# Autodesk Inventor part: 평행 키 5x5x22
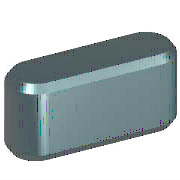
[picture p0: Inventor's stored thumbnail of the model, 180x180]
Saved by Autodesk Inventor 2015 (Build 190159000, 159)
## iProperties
IsCustomPart: 1
Created: 2012-02
Part Number: 평행 키 5x5x22
Material: 강철, 연강
Description: 평행 키
Document SubType Name: Modeling
Standard: JIS B 1301
Designer: mdu-01
Standards Organization: JIS
Language: ko-KR
Size Designation: 5x5x22
Categories: <MemberInstance><Categories><Category DisplayName="샤프트 부품" InternalName="7f7aeb1f-a693-4053-b835-cee3144e0d98" Mnemonic="SHFT"><Category DisplayName="키" Interna
Density: 1 g/cm^3
Appearance: 강철
Author: mdu-01
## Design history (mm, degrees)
workplane "Work Plane1"
workplane "Work Plane2"
sketch "스케치1"
  geometry: L1 (2.5, 2.5)-(19.5, 2.5); L2 (19.5, -2.5)-(2.5, -2.5); L3 (0, 9.4)-(0, -7.4) reference; L4 (-5, 0)-(30, 0) reference; L5 (22, 0)-(22, 7); A1 r 2.5 centre (2.5, 0) between (2.5, 2.5) and (2.5, -2.5); A2 r 2.5 centre (19.5, 0) between (19.5, -2.5) and (19.5, 2.5)
  constraints: 6 end point, 5 point on circle, 4 tangent, 3 point on line, 2 centre point, 1 horizontal, 1 parallel, 1 perpendicular
  dimensions: "d0" = 2.5 radius of A1 (= 0.5 x PB); "d13" = 2.5 radius of A2 (= 0.5 x PB); "d14" = 22 distance between parallel lines of L5 L3 (= NLG)
extrude "본체1" new body sketch "스케치1" taper "d3" = 0 deg; stored distance "d4" = 10
workplane "Work Plane3"
body "Solid1"
chamfer "모따기1" distance "d8" = 0.4 (= PHH); stored, may be unused: second distance "d9" = 0.4 (= PHH), angle "d15" = 45 deg
other parameters: "d1" = -3 (= -PNT), "d2" = 2 (= PH - PNT), "NLG" = 22 [user parameter; used in 3 equation terms], "PB" = 5 [user parameter; used in 2 equation terms], "PNT" = 3 [user parameter; used in 2 equation terms], "PH" = 5 [user parameter; used in 1 equation term], "PHH" = 0.4 [user parameter; used in 2 equation terms], "d10" = 0, "d16" = 0, "d17" = 0, "d18" = 0, "WDMIN" = 12 [user parameter], "PLB2" = 22 (= NLG) [user parameter], "WDMAX" = 17 [user parameter], "PLB1" = 22 (= NLG) [user parameter], "RR" = 0.16 [user parameter], "PUEB" = 2.3 [user parameter]
